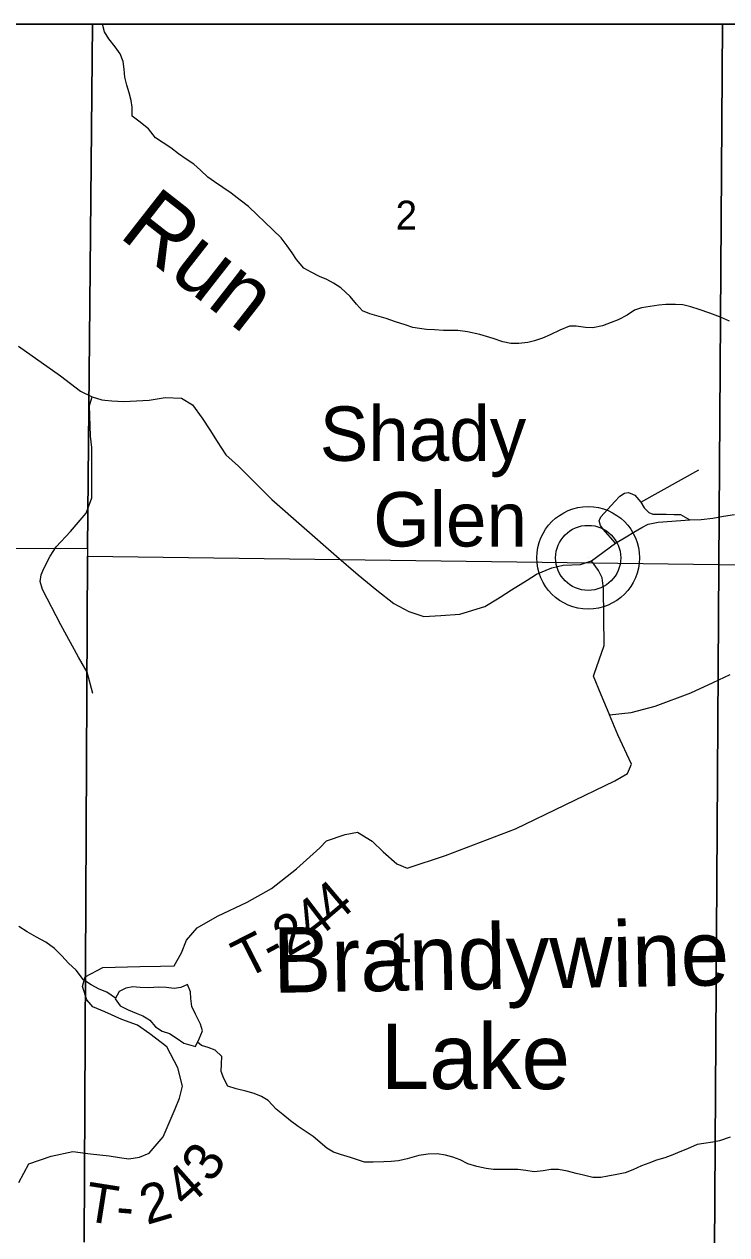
# Model space of a CAD drawing. Extents: x 2.1 to 8.9, y 14.1 to 20.9.
# Drawn here: x 5.459 to 6.478, y 19.144 to 20.9 of the extents above; entities that cross this region are included whole.
import ezdxf

# ---------------------------------------------------------------- set-up
doc = ezdxf.new("R2010")
doc.units = 0
for name, color, linetype in [('Default', 7, 'Continuous'), ('GM_X_City_Street', 7, 'Continuous'), ('GM_X_County_Road_Text', 7, 'Continuous'), ('GM_X_Interchange_Ramps', 7, 'Continuous'), ('GM_X_Major_River', 7, 'Continuous'), ('GM_X_Minor_River_Text', 7, 'Continuous'), ('GM_X_Rail_Line', 7, 'Continuous'), ('GM_X_State_Route', 7, 'Continuous'), ('GM_X_State_Shield', 7, 'Continuous'), ('GM_X_Township_Text', 7, 'Continuous'), ('PV_P_Text', 7, 'Continuous'), ('SH_Cut_Line', 7, 'Continuous'), ('SH_Data', 7, 'Continuous'), ('TX_P_Misc', 7, 'Continuous')]:
    doc.layers.add(name, color=color, linetype=linetype)

msp = doc.modelspace()

# ---------------------------------------------------------------- linework, layer by layer
at = {"layer": 'Default'}
for p, q in [((7.8225, 20.9), (2.1, 20.9)), ((5.558, 20.9), (4.5485, 20.9)), ((5.5506, 20.1397), (5.558, 20.9)), ((5.558, 20.9), (5.5506, 20.1397)), ((6.4715, 20.9), (5.558, 20.9)), ((6.4665, 20.1167), (6.4715, 20.9)), ((6.4715, 20.9), (6.4665, 20.1167)), ((7.4735, 20.9), (6.4715, 20.9)), ((4.5449, 20.1449), (5.5506, 20.1397)), ((5.5506, 20.1397), (5.5505, 20.1287)), ((5.5505, 20.1287), (6.4665, 20.1167)), ((6.4665, 20.1167), (7.4653, 20.105))]:
    msp.add_line(p, q, dxfattribs=at)
at = {"layer": 'GM_X_City_Street'}
for p, q in [((5.5537, 20.3469), (5.5573, 20.3596)), ((5.5549, 20.3024), (5.5537, 20.3469)), ((5.5571, 20.2864), (5.5549, 20.3024)), ((5.5569, 20.2395), (5.5571, 20.2864)), ((6.3533, 20.207), (6.4374, 20.2538)), ((5.5569, 20.2133), (5.5569, 20.2395)), ((5.5488, 20.191), (5.5569, 20.2133)), ((6.2953, 20.1856), (6.3156, 20.2081)), ((6.3156, 20.2081), (6.3229, 20.2155)), ((6.3229, 20.2155), (6.3296, 20.2198)), ((6.3296, 20.2198), (6.3348, 20.2207)), ((6.3348, 20.2207), (6.3379, 20.2199)), ((6.3379, 20.2199), (6.3443, 20.2172)), ((6.3443, 20.2172), (6.3533, 20.207)), ((6.3533, 20.207), (6.3582, 20.1989)), ((5.5371, 20.1773), (5.5488, 20.191)), ((6.3582, 20.1989), (6.3646, 20.1921)), ((6.3646, 20.1921), (6.3708, 20.1893)), ((6.3708, 20.1893), (6.3899, 20.1895)), ((6.3899, 20.1895), (6.4015, 20.1891)), ((6.4015, 20.1891), (6.4105, 20.1888)), ((6.4105, 20.1888), (6.4242, 20.1814)), ((5.526, 20.1642), (5.5371, 20.1773)), ((6.2928, 20.1799), (6.2953, 20.1856)), ((6.2946, 20.1731), (6.2928, 20.1799)), ((6.2984, 20.1679), (6.2946, 20.1731)), ((5.5054, 20.1423), (5.526, 20.1642)), ((6.3163, 20.1472), (6.2984, 20.1679)), ((5.4964, 20.1284), (5.5054, 20.1423)), ((5.4871, 20.1106), (5.4964, 20.1284)), ((6.2918, 20.108), (6.2817, 20.122)), ((5.4819, 20.0918), (5.4835, 20.1013)), ((5.4835, 20.1013), (5.4871, 20.1106)), ((6.2969, 20.097), (6.2918, 20.108)), ((5.4855, 20.0804), (5.4819, 20.0918)), ((6.2993, 20.0817), (6.2969, 20.097)), ((5.5118, 20.0291), (5.4855, 20.0804)), ((6.3, 19.999), (6.2993, 20.0817)), ((5.5376, 19.982), (5.5118, 20.0291)), ((6.2856, 19.9573), (6.3, 19.999)), ((5.55, 19.9603), (5.5376, 19.982)), ((5.5582, 19.9296), (5.55, 19.9603)), ((6.2847, 19.9546), (6.2856, 19.9573)), ((6.2957, 19.9273), (6.2847, 19.9546)), ((6.4257, 19.9304), (6.4579, 19.9452)), ((6.4579, 19.9452), (6.4828, 19.9569)), ((6.3071, 19.9001), (6.2957, 19.9273)), ((6.374, 19.9111), (6.4257, 19.9304)), ((6.3392, 19.9019), (6.374, 19.9111)), ((6.3078, 19.8986), (6.3071, 19.9001)), ((6.3078, 19.8986), (6.3392, 19.9019)), ((6.3198, 19.8696), (6.3078, 19.8986)), ((6.3395, 19.8268), (6.3198, 19.8696)), ((6.3337, 19.8132), (6.3395, 19.8268)), ((6.1712, 19.7331), (6.3156, 19.8026)), ((6.3156, 19.8026), (6.3337, 19.8132)), ((6.0701, 19.6945), (6.1712, 19.7331)), ((5.8876, 19.7054), (5.8974, 19.7157)), ((5.8974, 19.7157), (5.9246, 19.7252)), ((5.9246, 19.7252), (5.9422, 19.7283)), ((5.9422, 19.7283), (5.9636, 19.7152)), ((5.9636, 19.7152), (5.9794, 19.6996)), ((5.8538, 19.6754), (5.8876, 19.7054)), ((5.9794, 19.6996), (5.9995, 19.6822)), ((5.9995, 19.6822), (6.0141, 19.676)), ((6.0141, 19.676), (6.0701, 19.6945)), ((5.8176, 19.6468), (5.8538, 19.6754)), ((5.7822, 19.627), (5.8176, 19.6468)), ((5.7392, 19.6065), (5.7822, 19.627)), ((5.7097, 19.5896), (5.7392, 19.6065)), ((5.6943, 19.5715), (5.7097, 19.5896)), ((5.6868, 19.5533), (5.6943, 19.5715)), ((5.6766, 19.5346), (5.6868, 19.5533)), ((5.5472, 19.5186), (5.5727, 19.5323)), ((5.5727, 19.5323), (5.6267, 19.5336)), ((5.6267, 19.5336), (5.6566, 19.5341)), ((5.6566, 19.5341), (5.6766, 19.5346)), ((5.5433, 19.5044), (5.5472, 19.5186)), ((5.5498, 19.485), (5.5433, 19.5044)), ((5.5586, 19.4751), (5.5498, 19.485)), ((5.5759, 19.4679), (5.5586, 19.4751)), ((5.6007, 19.4565), (5.5759, 19.4679)), ((5.623, 19.4483), (5.6007, 19.4565)), ((5.6409, 19.4359), (5.623, 19.4483)), ((5.6656, 19.4172), (5.6409, 19.4359)), ((5.6817, 19.3868), (5.6656, 19.4172)), ((5.6885, 19.3598), (5.6817, 19.3868)), ((5.684, 19.3428), (5.6885, 19.3598)), ((5.6779, 19.327), (5.684, 19.3428)), ((5.6604, 19.2867), (5.6779, 19.327)), ((5.6399, 19.2627), (5.6604, 19.2867)), ((5.4655, 19.2473), (5.4982, 19.2587)), ((5.4982, 19.2587), (5.5293, 19.2654)), ((5.5293, 19.2654), (5.5552, 19.2619)), ((5.5552, 19.2619), (5.5822, 19.259)), ((5.5822, 19.259), (5.5971, 19.2566)), ((5.6262, 19.2571), (5.6399, 19.2627)), ((5.4511, 19.2205), (5.4655, 19.2473)), ((5.5971, 19.2566), (5.6108, 19.2545)), ((5.6108, 19.2545), (5.6262, 19.2571))]:
    msp.add_line(p, q, dxfattribs=at)
at = {"layer": 'GM_X_Interchange_Ramps'}
for p, q in [((4.5449, 20.1449), (5.5506, 20.1397)), ((5.5506, 20.1397), (5.5505, 20.1287)), ((5.5505, 20.1287), (5.5458, 19.1336)), ((5.5458, 19.1336), (5.5505, 20.1287)), ((5.5505, 20.1287), (6.4665, 20.1167)), ((6.4665, 20.1167), (6.4599, 19.1223)), ((6.4599, 19.1223), (6.4665, 20.1167)), ((6.4665, 20.1167), (7.4653, 20.105))]:
    msp.add_line(p, q, dxfattribs=at)
at = {"layer": 'GM_X_Rail_Line'}
for p, q in [((5.6166, 19.5041), (5.6064, 19.5019)), ((5.6272, 19.5029), (5.6166, 19.5041)), ((5.6542, 19.5038), (5.6394, 19.5025)), ((5.6649, 19.5029), (5.6542, 19.5038)), ((5.6959, 19.5073), (5.6862, 19.5032)), ((5.7001, 19.4968), (5.6959, 19.5073)), ((5.5966, 19.4974), (5.5909, 19.4866)), ((5.5909, 19.4866), (5.598, 19.4765)), ((5.6064, 19.5019), (5.5966, 19.4974)), ((5.6394, 19.5025), (5.6272, 19.5029)), ((5.6763, 19.5018), (5.6649, 19.5029)), ((5.6862, 19.5032), (5.6763, 19.5018)), ((5.7004, 19.4873), (5.7001, 19.4968)), ((5.7019, 19.4756), (5.7004, 19.4873)), ((5.598, 19.4765), (5.6096, 19.4708)), ((5.6096, 19.4708), (5.6212, 19.4658)), ((5.7075, 19.4644), (5.7019, 19.4756)), ((5.6212, 19.4658), (5.6308, 19.462)), ((5.6308, 19.462), (5.6382, 19.4576)), ((5.6382, 19.4576), (5.6413, 19.4558)), ((5.6413, 19.4558), (5.6492, 19.4462)), ((5.7148, 19.4501), (5.7075, 19.4644)), ((5.6492, 19.4462), (5.6589, 19.44)), ((5.6589, 19.44), (5.6696, 19.4366)), ((5.6696, 19.4366), (5.6793, 19.43)), ((5.7125, 19.4288), (5.7174, 19.4403)), ((5.7174, 19.4403), (5.7148, 19.4501)), ((5.6793, 19.43), (5.6902, 19.4224)), ((5.6902, 19.4224), (5.7071, 19.4176)), ((5.7071, 19.4176), (5.7125, 19.4288))]:
    msp.add_line(p, q, dxfattribs=at)
at = {"layer": 'GM_X_State_Route'}
for radius in [0.0744, 0.0472]:
    msp.add_circle((6.2768, 20.1261), radius, dxfattribs=at)
at = {"layer": 'GM_X_State_Shield'}
for p, q in [((5.4508, 20.4332), (5.5114, 20.3899)), ((5.5114, 20.3899), (5.5405, 20.3679)), ((5.5405, 20.3679), (5.5573, 20.3596)), ((5.5573, 20.3596), (5.5717, 20.3552)), ((5.5717, 20.3552), (5.5757, 20.3547)), ((5.5757, 20.3547), (5.5858, 20.3537)), ((5.5858, 20.3537), (5.6036, 20.3531)), ((5.6036, 20.3531), (5.64, 20.3549)), ((5.64, 20.3549), (5.6632, 20.3586)), ((5.6632, 20.3586), (5.6871, 20.3576)), ((5.6871, 20.3576), (5.7028, 20.3479)), ((5.7028, 20.3479), (5.717, 20.3285)), ((5.717, 20.3285), (5.7279, 20.3119)), ((5.7279, 20.3119), (5.7388, 20.2949)), ((5.7388, 20.2949), (5.7514, 20.2755)), ((5.7514, 20.2755), (5.7695, 20.2589)), ((5.7695, 20.2589), (5.8179, 20.2109)), ((5.8179, 20.2109), (5.9117, 20.1284)), ((6.4732, 20.1864), (6.489, 20.1892)), ((6.3547, 20.1702), (6.3638, 20.1748)), ((6.3638, 20.1748), (6.3782, 20.1778)), ((6.3782, 20.1778), (6.4242, 20.1814)), ((6.4242, 20.1814), (6.4406, 20.1818)), ((6.4406, 20.1818), (6.4575, 20.1836)), ((6.4575, 20.1836), (6.4732, 20.1864)), ((6.3163, 20.1472), (6.332, 20.1568)), ((6.332, 20.1568), (6.3431, 20.1632)), ((6.3431, 20.1632), (6.3547, 20.1702)), ((6.2817, 20.122), (6.3163, 20.1472)), ((5.9117, 20.1284), (5.9432, 20.1016)), ((6.2657, 20.1163), (6.2817, 20.122)), ((5.9432, 20.1016), (5.9705, 20.0794)), ((6.1884, 20.0936), (6.2021, 20.1026)), ((6.2021, 20.1026), (6.224, 20.1116)), ((6.224, 20.1116), (6.2405, 20.1153)), ((6.2405, 20.1153), (6.2657, 20.1163)), ((6.1657, 20.0797), (6.1884, 20.0936)), ((5.9705, 20.0794), (5.9948, 20.0598)), ((6.1268, 20.0557), (6.1453, 20.0665)), ((6.1453, 20.0665), (6.1494, 20.0692)), ((6.1494, 20.0692), (6.1657, 20.0797)), ((5.9948, 20.0598), (6.0169, 20.0485)), ((6.0169, 20.0485), (6.0384, 20.041)), ((6.0907, 20.0444), (6.1268, 20.0557)), ((6.0384, 20.041), (6.0629, 20.0427)), ((6.0629, 20.0427), (6.0907, 20.0444))]:
    msp.add_line(p, q, dxfattribs=at)
at = {"layer": 'GM_X_Township_Text'}
msp.add_line((6.2768, 20.1261), (6.2768, 20.1261), dxfattribs=at)
at = {"layer": 'SH_Cut_Line'}
msp.add_line((7.8225, 20.9), (2.1, 20.9), dxfattribs=at)
at = {"layer": 'SH_Data'}
msp.add_line((2.1, 20.9), (8.9, 20.9), dxfattribs=at)
msp.add_line((2.1, 20.9), (8.9, 20.9), dxfattribs=at)
at = {"layer": 'TX_P_Misc'}
for p, q in [((5.5751, 20.8891), (5.5724, 20.9)), ((5.5724, 20.9), (5.5724, 20.9)), ((5.5818, 20.8786), (5.5751, 20.8891)), ((5.591, 20.8671), (5.5818, 20.8786)), ((5.5981, 20.8571), (5.591, 20.8671)), ((5.6023, 20.8458), (5.5981, 20.8571)), ((5.6037, 20.8348), (5.6023, 20.8458)), ((5.6049, 20.8231), (5.6037, 20.8348)), ((5.6075, 20.8114), (5.6049, 20.8231)), ((5.6113, 20.8005), (5.6075, 20.8114)), ((5.6139, 20.7895), (5.6113, 20.8005)), ((5.6154, 20.7797), (5.6139, 20.7895)), ((5.6154, 20.7667), (5.6154, 20.7797)), ((5.6251, 20.7594), (5.6154, 20.7667)), ((5.6392, 20.7485), (5.6251, 20.7594)), ((5.6491, 20.7351), (5.6392, 20.7485)), ((5.6603, 20.7282), (5.6491, 20.7351)), ((5.6716, 20.7206), (5.6603, 20.7282)), ((5.6825, 20.7118), (5.6716, 20.7206)), ((5.6938, 20.7042), (5.6825, 20.7118)), ((5.705, 20.6969), (5.6938, 20.7042)), ((5.7148, 20.6885), (5.705, 20.6969)), ((5.7254, 20.6782), (5.7148, 20.6885)), ((5.7351, 20.6713), (5.7254, 20.6782)), ((5.7468, 20.6633), (5.7351, 20.6713)), ((5.7588, 20.6549), (5.7468, 20.6633)), ((5.772, 20.645), (5.7588, 20.6549)), ((5.7841, 20.6355), (5.772, 20.645)), ((5.7967, 20.6234), (5.7841, 20.6355)), ((5.8077, 20.6127), (5.7967, 20.6234)), ((5.8316, 20.5903), (5.8077, 20.6127)), ((5.8403, 20.5787), (5.8316, 20.5903)), ((5.8474, 20.5687), (5.8403, 20.5787)), ((5.8538, 20.559), (5.8474, 20.5687)), ((5.8645, 20.546), (5.8538, 20.559)), ((5.8749, 20.5403), (5.8645, 20.546)), ((5.8873, 20.5342), (5.8749, 20.5403)), ((5.8977, 20.53), (5.8873, 20.5342)), ((5.9074, 20.5246), (5.8977, 20.53)), ((5.9179, 20.5177), (5.9074, 20.5246)), ((5.9316, 20.5052), (5.9179, 20.5177)), ((5.9406, 20.4941), (5.9316, 20.5052)), ((5.9497, 20.4845), (5.9406, 20.4941)), ((6.3541, 20.4888), (6.3439, 20.4854)), ((6.3791, 20.4926), (6.3541, 20.4888)), ((6.3893, 20.4933), (6.3791, 20.4926)), ((6.4034, 20.4934), (6.3893, 20.4933)), ((6.414, 20.4929), (6.4034, 20.4934)), ((6.4259, 20.4903), (6.414, 20.4929)), ((6.4378, 20.4865), (6.4259, 20.4903)), ((5.9601, 20.4798), (5.9497, 20.4845)), ((5.9705, 20.4771), (5.9601, 20.4798)), ((5.9839, 20.473), (5.9705, 20.4771)), ((5.9973, 20.4685), (5.9839, 20.473)), ((6.3204, 20.4714), (6.3103, 20.4676)), ((6.3335, 20.4782), (6.3204, 20.4714)), ((6.3439, 20.4854), (6.3335, 20.4782)), ((6.4532, 20.4812), (6.4378, 20.4865)), ((6.4686, 20.4753), (6.4532, 20.4812)), ((6.4817, 20.4692), (6.4686, 20.4753)), ((6.0112, 20.464), (5.9973, 20.4685)), ((6.0227, 20.4601), (6.0112, 20.464)), ((6.0322, 20.4585), (6.0227, 20.4601)), ((6.0425, 20.4573), (6.0322, 20.4585)), ((6.054, 20.4569), (6.0425, 20.4573)), ((6.0669, 20.4558), (6.054, 20.4569)), ((6.078, 20.4558), (6.0669, 20.4558)), ((6.0878, 20.4557), (6.078, 20.4558)), ((6.102, 20.4539), (6.0878, 20.4557)), ((6.1196, 20.4499), (6.102, 20.4539)), ((6.2357, 20.4565), (6.2219, 20.4496)), ((6.2496, 20.4623), (6.2357, 20.4565)), ((6.2595, 20.4622), (6.2496, 20.4623)), ((6.2729, 20.4604), (6.2595, 20.4622)), ((6.2835, 20.4599), (6.2729, 20.4604)), ((6.2975, 20.4627), (6.2835, 20.4599)), ((6.3103, 20.4676), (6.2975, 20.4627)), ((6.1388, 20.4444), (6.1196, 20.4499)), ((6.153, 20.4395), (6.1388, 20.4444)), ((6.1645, 20.4372), (6.153, 20.4395)), ((6.1763, 20.4368), (6.1645, 20.4372)), ((6.1891, 20.4384), (6.1763, 20.4368)), ((6.1989, 20.4409), (6.1891, 20.4384)), ((6.2106, 20.4447), (6.1989, 20.4409)), ((6.2219, 20.4496), (6.2106, 20.4447)), ((5.4631, 19.5837), (5.4511, 19.5917)), ((5.4767, 19.5761), (5.4631, 19.5837)), ((5.4902, 19.5689), (5.4767, 19.5761)), ((5.5027, 19.5595), (5.4902, 19.5689)), ((5.5133, 19.5491), (5.5027, 19.5595)), ((5.5231, 19.5384), (5.5133, 19.5491)), ((5.5341, 19.5281), (5.5231, 19.5384)), ((5.5451, 19.5144), (5.5341, 19.5281)), ((5.556, 19.5068), (5.5451, 19.5144)), ((5.5676, 19.5007), (5.556, 19.5068)), ((5.5788, 19.4964), (5.5676, 19.5007)), ((5.5913, 19.4874), (5.5788, 19.4964)), ((5.7162, 19.419), (5.71, 19.4237)), ((5.7258, 19.4159), (5.7162, 19.419)), ((5.7358, 19.412), (5.7258, 19.4159)), ((5.7456, 19.4028), (5.7358, 19.412)), ((5.7451, 19.3925), (5.7456, 19.4028)), ((5.7447, 19.3815), (5.7451, 19.3925)), ((5.7485, 19.3713), (5.7447, 19.3815)), ((5.7541, 19.3601), (5.7485, 19.3713)), ((5.7664, 19.3563), (5.7541, 19.3601)), ((5.7802, 19.353), (5.7664, 19.3563)), ((5.7925, 19.3495), (5.7802, 19.353)), ((5.8029, 19.3449), (5.7925, 19.3495)), ((5.8126, 19.3391), (5.8029, 19.3449)), ((5.8244, 19.3266), (5.8126, 19.3391)), ((5.8341, 19.3189), (5.8244, 19.3266)), ((5.8451, 19.3097), (5.8341, 19.3189)), ((5.8564, 19.3013), (5.8451, 19.3097)), ((5.8676, 19.2937), (5.8564, 19.3013)), ((5.8781, 19.2868), (5.8676, 19.2937)), ((5.898, 19.2703), (5.8781, 19.2868)), ((6.4445, 19.2768), (6.4347, 19.2754)), ((6.4574, 19.2788), (6.4445, 19.2768)), ((6.4672, 19.2806), (6.4574, 19.2788)), ((6.4826, 19.286), (6.4672, 19.2806)), ((5.9077, 19.2642), (5.898, 19.2703)), ((5.9177, 19.2607), (5.9077, 19.2642)), ((5.9319, 19.2566), (5.9177, 19.2607)), ((6.0311, 19.2593), (6.0145, 19.2546)), ((6.0447, 19.2616), (6.0311, 19.2593)), ((6.0576, 19.2617), (6.0447, 19.2616)), ((6.0698, 19.2598), (6.0576, 19.2617)), ((6.0805, 19.2571), (6.0698, 19.2598)), ((6.3994, 19.2602), (6.3882, 19.2561)), ((6.4096, 19.2647), (6.3994, 19.2602)), ((6.4208, 19.2689), (6.4096, 19.2647)), ((6.4347, 19.2754), (6.4208, 19.2689)), ((5.9423, 19.2531), (5.9319, 19.2566)), ((5.9523, 19.25), (5.9423, 19.2531)), ((5.9652, 19.2496), (5.9523, 19.25)), ((5.9804, 19.2501), (5.9652, 19.2496)), ((5.991, 19.2508), (5.9804, 19.2501)), ((6.0016, 19.2519), (5.991, 19.2508)), ((6.0145, 19.2546), (6.0016, 19.2519)), ((6.0913, 19.2532), (6.0805, 19.2571)), ((6.1021, 19.2475), (6.0913, 19.2532)), ((6.1152, 19.2437), (6.1021, 19.2475)), ((6.129, 19.2407), (6.1152, 19.2437)), ((6.1397, 19.2391), (6.129, 19.2407)), ((6.3543, 19.2444), (6.3416, 19.2386)), ((6.3648, 19.2485), (6.3543, 19.2444)), ((6.3761, 19.2526), (6.3648, 19.2485)), ((6.3882, 19.2561), (6.3761, 19.2526)), ((6.1492, 19.2391), (6.1397, 19.2391)), ((6.1609, 19.2394), (6.1492, 19.2391)), ((6.1746, 19.2391), (6.1609, 19.2394)), ((6.1865, 19.2376), (6.1746, 19.2391)), ((6.1987, 19.236), (6.1865, 19.2376)), ((6.2116, 19.2372), (6.1987, 19.236)), ((6.2229, 19.2391), (6.2116, 19.2372)), ((6.2336, 19.2394), (6.2229, 19.2391)), ((6.2469, 19.2368), (6.2336, 19.2394)), ((6.2592, 19.2334), (6.2469, 19.2368)), ((6.2699, 19.2311), (6.2592, 19.2334)), ((6.2837, 19.2277), (6.2699, 19.2311)), ((6.2951, 19.2277), (6.2837, 19.2277)), ((6.3053, 19.2295), (6.2951, 19.2277)), ((6.3182, 19.2318), (6.3053, 19.2295)), ((6.3307, 19.2345), (6.3182, 19.2318)), ((6.3416, 19.2386), (6.3307, 19.2345))]:
    msp.add_line(p, q, dxfattribs=at)

# ---------------------------------------------------------------- texts
at = {"layer": 'GM_X_County_Road_Text'}
for s, p in [('2', (5.9975, 20.6022)), ('1', (5.9901, 19.5398))]:
    msp.add_text(s, height=0.0419, rotation=0, dxfattribs=at).set_placement(p)
at = {"layer": 'GM_X_Major_River'}
for s, p in [('Shady', (5.8875, 20.2668)), ('Glen', (5.965, 20.1426))]:
    msp.add_text(s, height=0.07898, rotation=0, dxfattribs=at).set_placement(p)
at = {"layer": 'GM_X_Minor_River_Text'}
for s, rotation, p in [('4', 40.2576, (5.9079, 19.5922)), ('4', 37.3884, (5.8777, 19.569)), ('2', 30.7115, (5.8416, 19.547)), ('T', 27.094, (5.7798, 19.5148)), ('-', 28.1552, (5.8186, 19.5347)), ('3', 57.5972, (5.7311, 19.2179)), ('4', 41.5447, (5.6937, 19.1816)), ('T', 351.028, (5.5442, 19.1653)), ('2', 16.4983, (5.6367, 19.1586)), ('-', 355.3046, (5.5908, 19.1582))]:
    msp.add_text(s, height=0.0568, rotation=rotation, dxfattribs=at).set_placement(p)
at = {"layer": 'PV_P_Text'}
for s, height, rotation, p in [('Run', 0.0947, 321.9751, (5.5941, 20.5928)), ('Brandywine', 0.09471, 0.9622, (5.8203, 19.4953)), ('Lake', 0.09471, 359.9627, (5.9759, 19.3559))]:
    msp.add_text(s, height=height, rotation=rotation, dxfattribs=at).set_placement(p)

doc.saveas('drawing.dxf')
